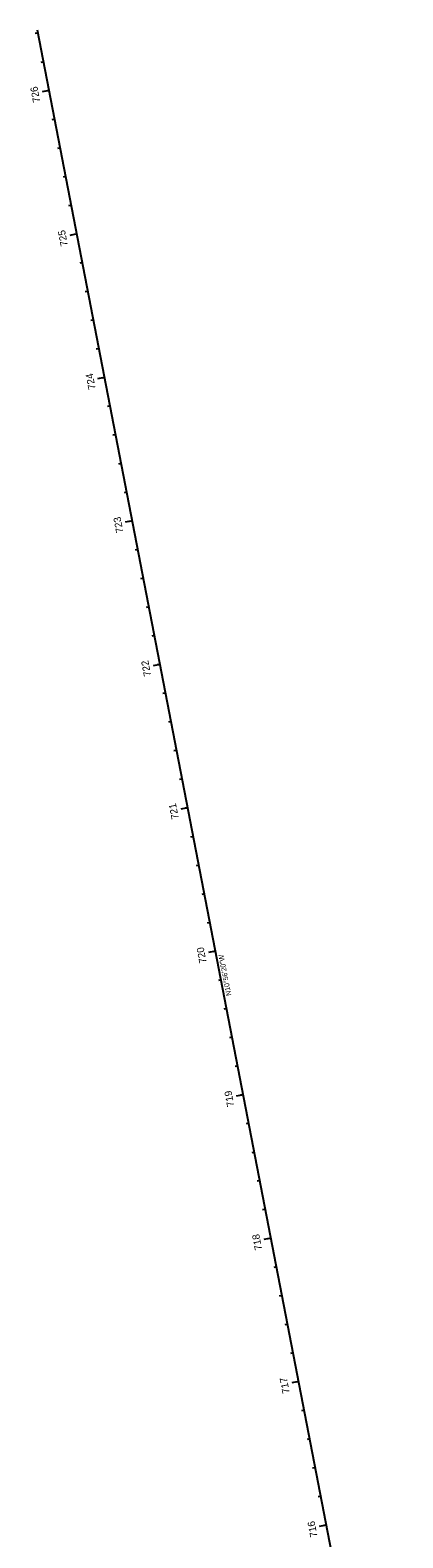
# Model space of a CAD drawing. Extents: x 2005660 to 2007493, y 401364 to 404817.
# Drawn here: x 2005660 to 2005915, y 403785 to 404817 of the extents above; entities that cross this region are included whole.
import ezdxf

# ---------------------------------------------------------------- set-up
doc = ezdxf.new("R2010")
doc.units = 0
for name, color, linetype in [('ConstLines', 7, 'Continuous'), ('CurbBack', 7, 'Continuous'), ('PavtAsphalt', 7, 'Continuous'), ('PavtAsphalt_ep', 7, 'Continuous'), ('PavtMilling', 7, 'Continuous'), ('ScratchEle_dp', 7, 'Continuous'), ('ShldrPaved', 7, 'Continuous'), ('TextAlgnTicks5000', 7, 'Continuous'), ('TrafSeparator', 7, 'Continuous')]:
    doc.layers.add(name, color=color, linetype=linetype)

msp = doc.modelspace()

# ---------------------------------------------------------------- linework, layer by layer
at = {"layer": 'PavtAsphalt'}
for p, q in [((2005665.5, 404815.2), (2005663.5, 404814.9)), ((2005669.3, 404795.6), (2005667.3, 404795.2)), ((2005673.1, 404776), (2005668.2, 404775)), ((2005676.9, 404756.3), (2005674.9, 404756)), ((2005680.7, 404736.7), (2005678.7, 404736.3)), ((2005684.5, 404717.1), (2005682.5, 404716.7)), ((2005688.3, 404697.4), (2005686.3, 404697)), ((2005692.1, 404677.8), (2005687.2, 404676.8)), ((2005695.9, 404658.2), (2005693.9, 404657.8)), ((2005699.7, 404638.5), (2005697.7, 404638.1)), ((2005703.5, 404618.9), (2005701.5, 404618.5)), ((2005707.2, 404599.2), (2005705.3, 404598.9)), ((2005711, 404579.6), (2005706.1, 404578.7)), ((2005714.8, 404560), (2005712.9, 404559.6)), ((2005718.6, 404540.3), (2005716.7, 404540)), ((2005722.4, 404520.7), (2005720.5, 404520.3)), ((2005726.2, 404501.1), (2005724.3, 404500.7)), ((2005730, 404481.4), (2005725.1, 404480.5)), ((2005733.8, 404461.8), (2005731.9, 404461.4)), ((2005737.6, 404442.2), (2005735.6, 404441.8)), ((2005741.4, 404422.5), (2005739.4, 404422.1)), ((2005745.2, 404402.9), (2005743.2, 404402.5)), ((2005749, 404383.2), (2005744.1, 404382.3)), ((2005752.8, 404363.6), (2005750.8, 404363.2)), ((2005756.6, 404344), (2005754.6, 404343.6)), ((2005760.4, 404324.3), (2005758.4, 404324)), ((2005764.2, 404304.7), (2005762.2, 404304.3)), ((2005768, 404285.1), (2005763.1, 404284.1)), ((2005771.8, 404265.4), (2005769.8, 404265)), ((2005775.6, 404245.8), (2005773.6, 404245.4)), ((2005779.4, 404226.2), (2005777.4, 404225.8)), ((2005783.2, 404206.5), (2005781.2, 404206.1)), ((2005786.9, 404186.9), (2005782, 404185.9)), ((2005790.7, 404167.2), (2005788.8, 404166.9)), ((2005794.5, 404147.6), (2005792.6, 404147.2)), ((2005798.3, 404128), (2005796.4, 404127.6)), ((2005802.1, 404108.3), (2005800.2, 404108)), ((2005805.9, 404088.7), (2005801, 404087.7)), ((2005809.7, 404069.1), (2005807.8, 404068.7)), ((2005813.5, 404049.4), (2005811.6, 404049)), ((2005817.3, 404029.8), (2005815.3, 404029.4)), ((2005821.1, 404010.1), (2005819.1, 404009.8)), ((2005824.9, 403990.5), (2005820, 403989.6)), ((2005828.7, 403970.9), (2005826.7, 403970.5)), ((2005832.5, 403951.2), (2005830.5, 403950.9)), ((2005836.3, 403931.6), (2005834.3, 403931.2)), ((2005840.1, 403912), (2005838.1, 403911.6)), ((2005843.9, 403892.3), (2005839, 403891.4)), ((2005847.7, 403872.7), (2005845.7, 403872.3)), ((2005851.5, 403853.1), (2005849.5, 403852.7)), ((2005855.3, 403833.4), (2005853.3, 403833)), ((2005859.1, 403813.8), (2005857.1, 403813.4)), ((2005862.9, 403794.1), (2005857.9, 403793.2))]:
    msp.add_line(p, q, dxfattribs=at)
at = {"layer": 'PavtAsphalt_ep'}
msp.add_line((2005915, 403524.1), (2005665.1, 404817.3), dxfattribs=at)
at = {"layer": 'ScratchEle_dp'}
for p, q in [((2005673.1, 404776), (2005671.1, 404775.6)), ((2005692.1, 404677.8), (2005687.2, 404676.8)), ((2005711, 404579.6), (2005709.1, 404579.2)), ((2005730, 404481.4), (2005728.1, 404481)), ((2005749, 404383.2), (2005747, 404382.9)), ((2005768, 404285.1), (2005766, 404284.7)), ((2005786.9, 404186.9), (2005782, 404185.9)), ((2005805.9, 404088.7), (2005804, 404088.3)), ((2005824.9, 403990.5), (2005822.9, 403990.1)), ((2005843.9, 403892.3), (2005841.9, 403891.9)), ((2005862.9, 403794.1), (2005860.9, 403793.8))]:
    msp.add_line(p, q, dxfattribs=at)
at = {"layer": 'TextAlgnTicks5000'}
msp.add_line((2005786.9, 404186.9), (2005785, 404186.5), dxfattribs=at)
at = {"layer": 'TrafSeparator'}
for p, q in [((2005673.1, 404776), (2005671.1, 404775.6)), ((2005711, 404579.6), (2005709.1, 404579.2)), ((2005749, 404383.2), (2005747, 404382.9)), ((2005786.9, 404186.9), (2005782, 404185.9)), ((2005824.9, 403990.5), (2005822.9, 403990.1)), ((2005862.9, 403794.1), (2005860.9, 403793.8))]:
    msp.add_line(p, q, dxfattribs=at)

# ---------------------------------------------------------------- texts
at = {"layer": 'ConstLines'}
for s, p in [('725', (2005685.9, 404669.9)), ('720', (2005780.8, 404179.1))]:
    msp.add_text(s, height=4.98, rotation=100.9389, dxfattribs=at).set_placement(p)
at = {"layer": 'CurbBack'}
msp.add_text('720', height=4.98, rotation=100.9389, dxfattribs=at).set_placement((2005780.8, 404179.1))
at = {"layer": 'PavtMilling'}
for s, p in [('726', (2005667, 404768.2)), ('725', (2005685.9, 404669.9)), ('724', (2005704.9, 404571.8)), ('723', (2005723.9, 404473.6)), ('722', (2005742.9, 404375.4)), ('721', (2005761.8, 404277.6)), ('720', (2005780.8, 404179.1)), ('719', (2005799.8, 404080.9)), ('718', (2005818.8, 403982.7)), ('717', (2005837.7, 403884.6)), ('716', (2005856.7, 403786.3))]:
    msp.add_text(s, height=4.98, rotation=100.9389, dxfattribs=at).set_placement(p)
at = {"layer": 'ShldrPaved'}
msp.add_text('N10°56\'20"W', height=3.48, rotation=100.9389, dxfattribs=at).set_placement((2005797.7, 404156.7))

doc.saveas('drawing.dxf')
